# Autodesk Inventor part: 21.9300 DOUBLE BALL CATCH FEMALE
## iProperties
Created: 2010-11
Part Number: 21.9300 DOUBLE BALL CATCH FEMALE
Document SubType Name: Modeling
Designer: Administrator
Density: 1.06 g/cm^3
Material: ABS Plastic
Mass: 18.2341 g
Surface Area: 76.525 cm^2
Volume: 17.202 cm^3
Author: Administrator
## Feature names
1. Base1
